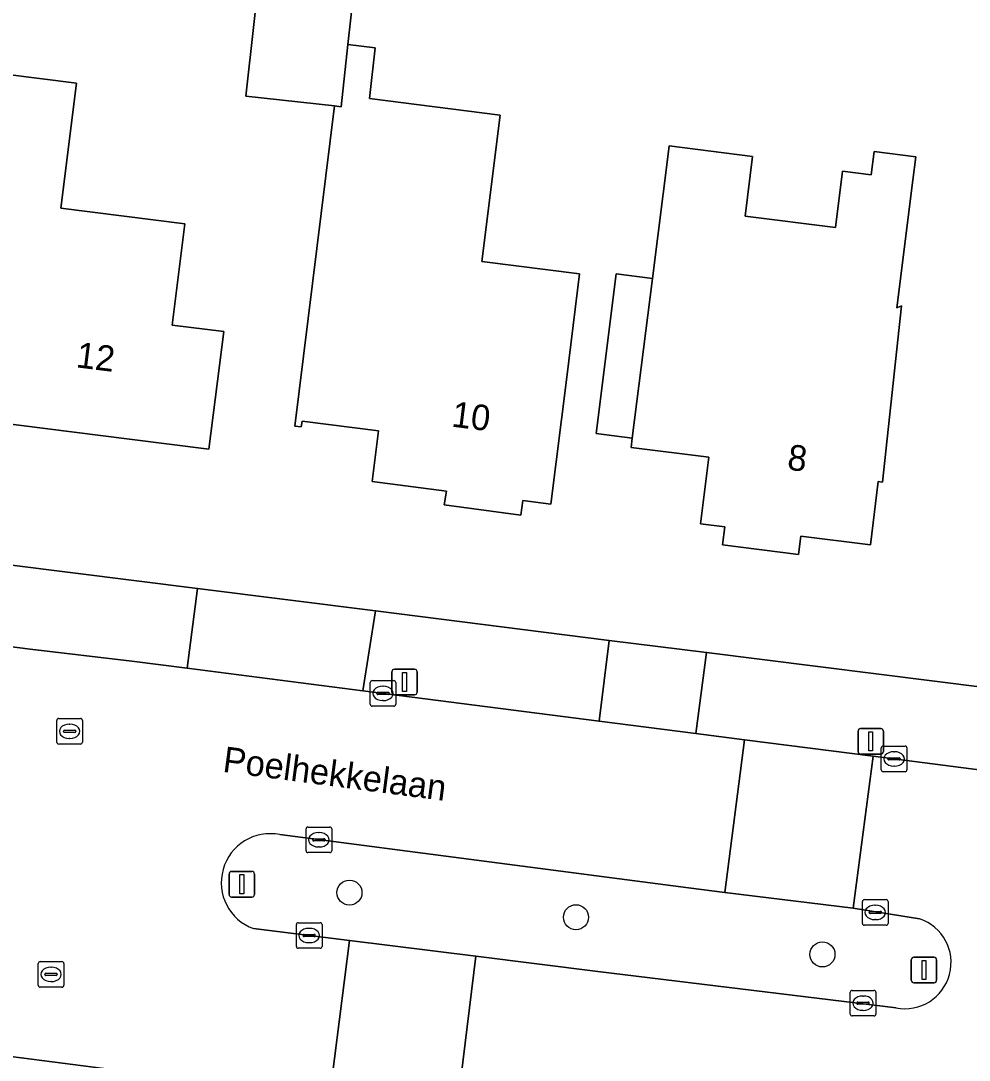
# Model space of a CAD drawing. Extents: x 161258 to 161838, y 380833 to 381727.
# Drawn here: x 161662.78 to 161699.84, y 381337.3 to 381377.89 of the extents above; entities that cross this region are included whole.
import ezdxf

# ---------------------------------------------------------------- set-up
doc = ezdxf.new("R2010")
doc.units = 0
for name, color, linetype in [('IMGEO_Berm_groen', 7, 'Continuous'), ('IMGEO_Boom', 7, 'Continuous'), ('IMGEO_Erf', 7, 'Continuous'), ('IMGEO_Kolk', 7, 'Continuous'), ('IMGEO_Lichtmast', 7, 'Continuous'), ('IMGEO_Openbare_ruimte_label', 7, 'Continuous'), ('IMGEO_Pand', 7, 'Continuous'), ('IMGEO_Pand_nummerreeks', 7, 'Continuous'), ('IMGEO_Rijbaan_lokaal_open', 7, 'Continuous'), ('IMGEO_Rioolput', 7, 'Continuous'), ('IMGEO_Verkeersbordpaal', 7, 'Continuous'), ('IMGEO_Voetpad_open', 7, 'Continuous')]:
    doc.layers.add(name, color=color, linetype=linetype)

msp = doc.modelspace()

# ---------------------------------------------------------------- linework, layer by layer
at = {"layer": 'IMGEO_Berm_groen'}
for points in [[(161695.307, 381343.233), (161690.292, 381343.852), (161688.874, 381344.034), (161672.903, 381346.109)], [(161697.905, 381342.825), (161695.307, 381343.233)], [(161671.878, 381342.439), (161675.625, 381341.974), (161680.569, 381341.362), (161685.333, 381340.771), (161696.981, 381339.343)]]:
    msp.add_lwpolyline(points, dxfattribs=at)
for centre, radius, start, end in [((161672.528, 381344.236), 1.911, 78.6811, 250.1097), ((161697.328, 381341.114), 1.805, 258.9062, 71.3703)]:
    msp.add_arc(centre, radius, start, end, dxfattribs=at)
at = {"layer": 'IMGEO_Boom'}
for centre in [(161675.627, 381343.846), (161684.477, 381342.885), (161694.108, 381341.432)]:
    msp.add_circle(centre, 0.489, dxfattribs=at)
at = {"layer": 'IMGEO_Erf'}
for points in [[(161649.876, 381358.212), (161669.686, 381355.721), (161676.646, 381354.846), (161685.778, 381353.698), (161689.572, 381353.221), (161700.55, 381351.841), (161703.323, 381376.439), (161703.682, 381379.623), (161710.363, 381438.89), (161702.199, 381460.88)], [(161675.92, 381380.099), (161675.568, 381376.965), (161676.626, 381376.832), (161676.405, 381374.855), (161681.514, 381374.212), (161680.793, 381368.487), (161684.619, 381368.006), (161684.113, 381363.979), (161683.489, 381359.018), (161682.396, 381359.155), (161682.32, 381358.586), (161679.33, 381358.984), (161679.421, 381359.53), (161676.507, 381359.896), (161676.757, 381361.886), (161673.774, 381362.255), (161673.745, 381362.031), (161673.486, 381362.065), (161675.044, 381374.567), (161671.58, 381374.956), (161672.207, 381380.555)]]:
    msp.add_lwpolyline(points, dxfattribs=at)
for points in [[(161664.964, 381375.453), (161664.351, 381370.574), (161669.196, 381369.965), (161668.698, 381366.006), (161670.713, 381365.753), (161670.136, 381361.169), (161667.027, 381361.559), (161660.531, 381362.376), (161660.47, 381361.885), (161655.947, 381362.454), (161656.003, 381362.9), (161652.899, 381363.29), (161653.522, 381368.251), (161654.621, 381377.046), (161658.181, 381376.613), (161657.832, 381373.841), (161661.873, 381373.334), (161662.175, 381375.804)], [(161696.014, 381371.878), (161696.128, 381372.789), (161697.755, 381372.585), (161697.64, 381371.674), (161697.012, 381366.68), (161697.195, 381366.757), (161696.455, 381359.88), (161696.29, 381359.901), (161695.978, 381357.422), (161693.256, 381357.764), (161693.166, 381357.052), (161690.204, 381357.425), (161690.293, 381358.129), (161689.341, 381358.249), (161689.668, 381360.851), (161686.632, 381361.234), (161686.678, 381361.597), (161685.265, 381361.775), (161686.049, 381368.013), (161687.462, 381367.833), (161688.086, 381372.794), (161688.113, 381373.009), (161691.379, 381372.599), (161691.085, 381370.267), (161694.615, 381369.824), (161694.891, 381372.019)]]:
    msp.add_lwpolyline(points, close=True, dxfattribs=at)
at = {"layer": 'IMGEO_Kolk'}
for p, q in [((161676.436, 381351.199), (161676.436, 381352.051)), ((161676.511, 381352.125), (161677.363, 381352.125)), ((161676.924, 381351.905), (161676.949, 381351.905)), ((161677.437, 381352.051), (161677.437, 381351.199)), ((161676.695, 381351.619), (161676.695, 381351.631)), ((161677.133, 381351.582), (161676.735, 381351.582)), ((161676.738, 381351.668), (161677.136, 381351.668)), ((161676.947, 381351.345), (161676.922, 381351.345)), ((161677.179, 381351.631), (161677.179, 381351.619)), ((161677.363, 381351.125), (161676.511, 381351.125)), ((161696.407, 381348.642), (161696.407, 381349.494)), ((161696.482, 381349.568), (161697.334, 381349.568)), ((161696.895, 381349.348), (161696.92, 381349.348)), ((161697.408, 381349.494), (161697.408, 381348.642)), ((161696.666, 381349.062), (161696.666, 381349.074)), ((161697.104, 381349.025), (161696.706, 381349.025)), ((161696.709, 381349.111), (161697.107, 381349.111)), ((161697.15, 381349.074), (161697.15, 381349.062)), ((161697.334, 381348.568), (161696.482, 381348.568)), ((161696.918, 381348.788), (161696.893, 381348.788)), ((161673.93, 381345.482), (161673.93, 381346.334)), ((161674.005, 381346.408), (161674.857, 381346.408)), ((161674.418, 381346.188), (161674.443, 381346.188)), ((161674.931, 381346.334), (161674.931, 381345.482)), ((161674.189, 381345.902), (161674.189, 381345.914)), ((161674.627, 381345.865), (161674.229, 381345.865)), ((161674.232, 381345.951), (161674.63, 381345.951)), ((161674.673, 381345.914), (161674.673, 381345.902)), ((161674.857, 381345.408), (161674.005, 381345.408)), ((161674.441, 381345.628), (161674.416, 381345.628)), ((161695.669, 381342.645), (161695.669, 381343.497)), ((161695.744, 381343.571), (161696.596, 381343.571)), ((161696.157, 381343.351), (161696.182, 381343.351)), ((161696.67, 381343.497), (161696.67, 381342.645)), ((161695.928, 381343.065), (161695.928, 381343.077)), ((161696.366, 381343.028), (161695.968, 381343.028)), ((161695.971, 381343.114), (161696.369, 381343.114)), ((161696.412, 381343.077), (161696.412, 381343.065)), ((161673.553, 381341.745), (161673.553, 381342.597)), ((161673.628, 381342.671), (161674.48, 381342.671)), ((161674.041, 381342.451), (161674.066, 381342.451)), ((161674.554, 381342.597), (161674.554, 381341.745)), ((161696.596, 381342.571), (161695.744, 381342.571)), ((161696.18, 381342.791), (161696.155, 381342.791)), ((161673.812, 381342.165), (161673.812, 381342.177)), ((161674.25, 381342.128), (161673.852, 381342.128)), ((161673.855, 381342.214), (161674.253, 381342.214)), ((161674.296, 381342.177), (161674.296, 381342.165)), ((161674.48, 381341.671), (161673.628, 381341.671)), ((161674.064, 381341.891), (161674.039, 381341.891)), ((161695.267, 381340.028), (161696.119, 381340.028)), ((161695.192, 381339.102), (161695.192, 381339.954)), ((161695.68, 381339.808), (161695.705, 381339.808)), ((161696.193, 381339.954), (161696.193, 381339.102)), ((161695.451, 381339.522), (161695.451, 381339.534)), ((161695.889, 381339.485), (161695.491, 381339.485)), ((161695.494, 381339.571), (161695.892, 381339.571)), ((161695.703, 381339.248), (161695.678, 381339.248)), ((161695.935, 381339.534), (161695.935, 381339.522)), ((161696.119, 381339.028), (161695.267, 381339.028))]:
    msp.add_line(p, q, dxfattribs=at)
for points in [[(161676.436, 381351.199), (161676.436, 381352.051)], [(161676.511, 381352.125), (161677.363, 381352.125)], [(161677.437, 381352.051), (161677.437, 381351.199)], [(161677.363, 381351.125), (161676.511, 381351.125)], [(161696.407, 381348.642), (161696.407, 381349.494)], [(161696.482, 381349.568), (161697.334, 381349.568)], [(161697.408, 381349.494), (161697.408, 381348.642)], [(161697.334, 381348.568), (161696.482, 381348.568)], [(161673.93, 381345.482), (161673.93, 381346.334)], [(161674.005, 381346.408), (161674.857, 381346.408)], [(161674.931, 381346.334), (161674.931, 381345.482)], [(161674.857, 381345.408), (161674.005, 381345.408)], [(161695.669, 381342.645), (161695.669, 381343.497)], [(161695.744, 381343.571), (161696.596, 381343.571)], [(161696.67, 381343.497), (161696.67, 381342.645)], [(161673.553, 381341.745), (161673.553, 381342.597)], [(161673.628, 381342.671), (161674.48, 381342.671)], [(161674.554, 381342.597), (161674.554, 381341.745)], [(161696.596, 381342.571), (161695.744, 381342.571)], [(161674.48, 381341.671), (161673.628, 381341.671)], [(161695.267, 381340.028), (161696.119, 381340.028)], [(161695.192, 381339.102), (161695.192, 381339.954)], [(161696.193, 381339.954), (161696.193, 381339.102)], [(161696.119, 381339.028), (161695.267, 381339.028)]]:
    msp.add_lwpolyline(points, dxfattribs=at)
for centre, radius, start, end in [((161676.513, 381352.049), 0.0765, 91.552, 178.448), ((161676.513, 381352.049), 0.0765, 91.552, 178.448), ((161677.361, 381352.049), 0.0765, 1.552, 88.448), ((161677.361, 381352.049), 0.0765, 1.552, 88.448), ((161676.735, 381351.628), 0.0403, 85.8775, 175.7526), ((161676.732, 381351.618), 0.0366, 178.938, 274.7102), ((161677.136, 381351.625), 0.043, 264.8664, 352.4533), ((161677.14, 381351.63), 0.0386, 1.7309, 96.639), ((161676.513, 381351.201), 0.0765, 181.552, 268.448), ((161676.513, 381351.201), 0.0765, 181.552, 268.448), ((161677.361, 381351.201), 0.0765, 271.552, 358.448), ((161677.361, 381351.201), 0.0765, 271.552, 358.448), ((161696.484, 381349.492), 0.0765, 91.552, 178.448), ((161696.484, 381349.492), 0.0765, 91.552, 178.448), ((161697.332, 381349.492), 0.0765, 1.552, 88.448), ((161697.332, 381349.492), 0.0765, 1.552, 88.448), ((161696.706, 381349.071), 0.0403, 85.8775, 175.7526), ((161696.703, 381349.061), 0.0366, 178.938, 274.7102), ((161697.107, 381349.068), 0.043, 264.8664, 352.4533), ((161697.111, 381349.073), 0.0386, 1.7309, 96.639), ((161696.484, 381348.644), 0.0765, 181.552, 268.448), ((161696.484, 381348.644), 0.0765, 181.552, 268.448), ((161697.332, 381348.644), 0.0765, 271.552, 358.448), ((161697.332, 381348.644), 0.0765, 271.552, 358.448), ((161674.007, 381346.332), 0.0765, 91.552, 178.448), ((161674.007, 381346.332), 0.0765, 91.552, 178.448), ((161674.855, 381346.332), 0.0765, 1.552, 88.448), ((161674.855, 381346.332), 0.0765, 1.552, 88.448), ((161674.229, 381345.911), 0.0403, 85.8775, 175.7526), ((161674.226, 381345.901), 0.0366, 178.938, 274.7102), ((161674.63, 381345.908), 0.043, 264.8664, 352.4533), ((161674.634, 381345.913), 0.0386, 1.7309, 96.639), ((161674.007, 381345.484), 0.0765, 181.552, 268.448), ((161674.007, 381345.484), 0.0765, 181.552, 268.448), ((161674.855, 381345.484), 0.0765, 271.552, 358.448), ((161674.855, 381345.484), 0.0765, 271.552, 358.448), ((161695.746, 381343.495), 0.0765, 91.552, 178.448), ((161695.746, 381343.495), 0.0765, 91.552, 178.448), ((161696.594, 381343.495), 0.0765, 1.552, 88.448), ((161696.594, 381343.495), 0.0765, 1.552, 88.448), ((161695.968, 381343.074), 0.0403, 85.8775, 175.7526), ((161695.965, 381343.064), 0.0366, 178.938, 274.7102), ((161696.369, 381343.071), 0.043, 264.8664, 352.4533), ((161696.373, 381343.076), 0.0386, 1.7309, 96.639), ((161673.63, 381342.595), 0.0765, 91.552, 178.448), ((161673.63, 381342.595), 0.0765, 91.552, 178.448), ((161674.478, 381342.595), 0.0765, 1.552, 88.448), ((161674.478, 381342.595), 0.0765, 1.552, 88.448), ((161695.746, 381342.647), 0.0765, 181.552, 268.448), ((161695.746, 381342.647), 0.0765, 181.552, 268.448), ((161696.594, 381342.647), 0.0765, 271.552, 358.448), ((161696.594, 381342.647), 0.0765, 271.552, 358.448), ((161673.852, 381342.174), 0.0403, 85.8775, 175.7526), ((161673.849, 381342.164), 0.0366, 178.938, 274.7102), ((161674.253, 381342.171), 0.043, 264.8664, 352.4533), ((161674.257, 381342.176), 0.0386, 1.7309, 96.639), ((161673.63, 381341.747), 0.0765, 181.552, 268.448), ((161673.63, 381341.747), 0.0765, 181.552, 268.448), ((161674.478, 381341.747), 0.0765, 271.552, 358.448), ((161674.478, 381341.747), 0.0765, 271.552, 358.448), ((161695.269, 381339.952), 0.0765, 91.552, 178.448), ((161695.269, 381339.952), 0.0765, 91.552, 178.448), ((161696.117, 381339.952), 0.0765, 1.552, 88.448), ((161696.117, 381339.952), 0.0765, 1.552, 88.448), ((161695.491, 381339.531), 0.0403, 85.8775, 175.7526), ((161695.488, 381339.521), 0.0366, 178.938, 274.7102), ((161695.892, 381339.528), 0.043, 264.8664, 352.4533), ((161695.896, 381339.533), 0.0386, 1.7309, 96.639), ((161695.269, 381339.104), 0.0765, 181.552, 268.448), ((161695.269, 381339.104), 0.0765, 181.552, 268.448), ((161696.117, 381339.104), 0.0765, 271.552, 358.448), ((161696.117, 381339.104), 0.0765, 271.552, 358.448)]:
    msp.add_arc(centre, radius, start, end, dxfattribs=at)
for centre, major_axis, ratio, start_param, end_param in [((161676.923, 381351.625), (-0.387, 0.002), 0.722429, 4.712389, 7.853982), ((161676.948, 381351.625), (-0.39, 0.002), 0.717154, 1.570796, 4.712389), ((161696.894, 381349.068), (-0.387, 0.002), 0.722429, 4.712389, 7.853982), ((161696.919, 381349.068), (-0.39, 0.002), 0.717154, 1.570796, 4.712389), ((161674.417, 381345.908), (-0.387, 0.002), 0.722429, 4.712389, 7.853982), ((161674.442, 381345.908), (-0.39, 0.002), 0.717154, 1.570796, 4.712389), ((161696.156, 381343.071), (-0.387, 0.002), 0.722429, 4.712389, 7.853982), ((161696.181, 381343.071), (-0.39, 0.002), 0.717154, 1.570796, 4.712389), ((161674.04, 381342.171), (-0.387, 0.002), 0.722429, 4.712389, 7.853982), ((161674.065, 381342.171), (-0.39, 0.002), 0.717154, 1.570796, 4.712389), ((161695.679, 381339.528), (-0.387, 0.002), 0.722429, 4.712389, 7.853982), ((161695.704, 381339.528), (-0.39, 0.002), 0.717154, 1.570796, 4.712389)]:
    msp.add_ellipse(centre, major_axis=major_axis, ratio=ratio, start_param=start_param, end_param=end_param, dxfattribs=at)
at = {"layer": 'IMGEO_Lichtmast'}
for p, q in [((161677.381, 381352.573), (161678.171, 381352.573)), ((161678.171, 381352.573), (161677.381, 381352.573)), ((161677.281, 381351.673), (161677.281, 381352.473)), ((161677.281, 381352.473), (161677.281, 381351.673)), ((161678.271, 381352.473), (161678.271, 381351.673)), ((161678.271, 381351.673), (161678.271, 381352.473)), ((161678.171, 381351.573), (161677.381, 381351.573)), ((161677.381, 381351.573), (161678.171, 381351.573)), ((161695.498, 381349.352), (161695.498, 381350.152)), ((161695.498, 381350.152), (161695.498, 381349.352)), ((161695.598, 381350.252), (161696.388, 381350.252)), ((161696.388, 381350.252), (161695.598, 381350.252)), ((161696.488, 381350.152), (161696.488, 381349.352)), ((161696.488, 381349.352), (161696.488, 381350.152)), ((161696.388, 381349.252), (161695.598, 381349.252)), ((161695.598, 381349.252), (161696.388, 381349.252))]:
    msp.add_line(p, q, dxfattribs=at)
for points in [[(161677.701, 381352.448), (161677.851, 381352.448), (161677.851, 381351.698), (161677.701, 381351.698), (161677.701, 381352.448)], [(161695.918, 381350.127), (161696.068, 381350.127), (161696.068, 381349.377), (161695.918, 381349.377), (161695.918, 381350.127)]]:
    msp.add_lwpolyline(points, dxfattribs=at)
for centre, start, end in [((161677.381, 381352.473), 90, 180), ((161677.381, 381352.473), 90, 180), ((161678.171, 381352.473), 0, 90), ((161678.171, 381352.473), 360, 90), ((161677.381, 381351.673), 180, 270), ((161677.381, 381351.673), 180, 270), ((161678.171, 381351.673), 270, 0), ((161678.171, 381351.673), 270, 0), ((161695.598, 381350.152), 90, 180), ((161695.598, 381350.152), 90, 180), ((161696.388, 381350.152), 0, 90), ((161696.388, 381350.152), 360, 90), ((161695.598, 381349.352), 180, 270), ((161695.598, 381349.352), 180, 270), ((161696.388, 381349.352), 270, 0), ((161696.388, 381349.352), 270, 0)]:
    msp.add_arc(centre, 0.1, start, end, dxfattribs=at)
at = {"layer": 'IMGEO_Pand'}
for points in [[(161675.92, 381380.099), (161675.099, 381380.191), (161672.207, 381380.555), (161671.58, 381374.956), (161675.044, 381374.567), (161675.297, 381374.539), (161675.568, 381376.965)], [(161684.619, 381368.006), (161680.793, 381368.487), (161681.514, 381374.212), (161676.405, 381374.855), (161676.626, 381376.832), (161675.568, 381376.965), (161675.297, 381374.539), (161675.044, 381374.567), (161673.486, 381362.065), (161673.745, 381362.031), (161673.774, 381362.255), (161676.757, 381361.886), (161676.507, 381359.896), (161679.421, 381359.53), (161679.33, 381358.984), (161682.32, 381358.586), (161682.396, 381359.155), (161683.489, 381359.018), (161684.113, 381363.979)], [(161669.196, 381369.965), (161664.351, 381370.574), (161664.964, 381375.453), (161662.175, 381375.804), (161661.873, 381373.334), (161660.531, 381362.376), (161667.027, 381361.559), (161670.136, 381361.169), (161670.713, 381365.753), (161668.698, 381366.006)], [(161697.195, 381366.757), (161697.012, 381366.68), (161697.64, 381371.674), (161697.755, 381372.585), (161696.128, 381372.789), (161696.014, 381371.878), (161694.891, 381372.019), (161694.615, 381369.824), (161691.085, 381370.267), (161691.379, 381372.599), (161688.113, 381373.009), (161688.086, 381372.794), (161687.462, 381367.833), (161686.678, 381361.597), (161686.632, 381361.234), (161689.668, 381360.851), (161689.341, 381358.249), (161690.293, 381358.129), (161690.204, 381357.425), (161693.166, 381357.052), (161693.256, 381357.764), (161695.978, 381357.422), (161696.29, 381359.901), (161696.455, 381359.88)], [(161687.462, 381367.833), (161686.049, 381368.013), (161685.265, 381361.775), (161686.678, 381361.597)]]:
    msp.add_lwpolyline(points, close=True, dxfattribs=at)
at = {"layer": 'IMGEO_Rijbaan_lokaal_open'}
for points in [[(161672.903, 381346.109), (161688.874, 381344.034), (161690.292, 381343.852), (161691.062, 381349.816), (161689.165, 381350.059), (161685.382, 381350.543), (161676.146, 381351.726), (161669.284, 381352.605), (161667.128, 381352.881), (161663.154, 381353.357), (161649.504, 381355.102), (161646.108, 381355.537), (161640.396, 381356.267), (161639.527, 381350.255), (161646.91, 381349.34), (161656.896, 381348.015)], [(161615.494, 381349.658), (161611.074, 381350.179), (161610.322, 381344.022), (161617.366, 381343.162), (161619.037, 381342.946), (161619.159, 381342.93), (161622.743, 381342.5), (161629.126, 381341.734), (161631.389, 381341.442), (161638.808, 381340.484), (161640.8, 381340.227), (161650.536, 381338.943), (161657.935, 381338.014), (161669.261, 381336.557), (161669.258, 381336.54), (161674.844, 381335.829), (161675.625, 381341.974), (161671.878, 381342.439)], [(161708.88, 381346.759), (161708.995, 381347.495), (161708.497, 381347.56), (161701.97, 381348.417), (161701.538, 381348.474), (161696.089, 381349.172), (161695.307, 381343.233), (161697.905, 381342.825)], [(161696.981, 381339.343), (161685.333, 381340.771), (161680.569, 381341.362), (161679.804, 381335.202), (161687.626, 381334.23), (161690.979, 381333.814), (161700.036, 381332.619), (161701.883, 381332.375)], [(161669.258, 381336.54), (161669.261, 381336.557), (161657.935, 381338.014)]]:
    msp.add_lwpolyline(points, dxfattribs=at)
for points in [[(161696.089, 381349.172), (161691.062, 381349.816), (161690.292, 381343.852), (161695.307, 381343.233)], [(161674.844, 381335.829), (161678.715, 381335.337), (161679.804, 381335.202), (161680.569, 381341.362), (161675.625, 381341.974)]]:
    msp.add_lwpolyline(points, close=True, dxfattribs=at)
for centre, radius, start, end in [((161672.528, 381344.236), 1.911, 78.6811, 250.1097), ((161697.328, 381341.114), 1.805, 258.9062, 71.3703)]:
    msp.add_arc(centre, radius, start, end, dxfattribs=at)
at = {"layer": 'IMGEO_Rioolput'}
for p, q in [((161664.191, 381349.721), (161664.191, 381350.573)), ((161664.266, 381350.647), (161665.118, 381350.647)), ((161665.192, 381350.573), (161665.192, 381349.721)), ((161664.45, 381350.141), (161664.45, 381350.153)), ((161664.493, 381350.19), (161664.891, 381350.19)), ((161664.679, 381350.427), (161664.704, 381350.427)), ((161664.934, 381350.153), (161664.934, 381350.141)), ((161664.888, 381350.104), (161664.49, 381350.104)), ((161664.702, 381349.867), (161664.677, 381349.867)), ((161665.118, 381349.647), (161664.266, 381349.647)), ((161663.466, 381340.225), (161663.466, 381341.077)), ((161663.541, 381341.151), (161664.393, 381341.151)), ((161663.954, 381340.931), (161663.979, 381340.931)), ((161664.467, 381341.077), (161664.467, 381340.225)), ((161663.725, 381340.645), (161663.725, 381340.657)), ((161664.163, 381340.608), (161663.765, 381340.608)), ((161663.768, 381340.694), (161664.166, 381340.694)), ((161664.209, 381340.657), (161664.209, 381340.645)), ((161664.393, 381340.151), (161663.541, 381340.151)), ((161663.977, 381340.371), (161663.952, 381340.371))]:
    msp.add_line(p, q, dxfattribs=at)
for points in [[(161664.191, 381349.721), (161664.191, 381350.573)], [(161664.266, 381350.647), (161665.118, 381350.647)], [(161665.192, 381350.573), (161665.192, 381349.721)], [(161665.118, 381349.647), (161664.266, 381349.647)], [(161663.466, 381340.225), (161663.466, 381341.077)], [(161663.541, 381341.151), (161664.393, 381341.151)], [(161664.467, 381341.077), (161664.467, 381340.225)], [(161664.393, 381340.151), (161663.541, 381340.151)]]:
    msp.add_lwpolyline(points, dxfattribs=at)
for centre, radius, start, end in [((161664.268, 381350.571), 0.0765, 91.552, 178.448), ((161664.268, 381350.571), 0.0765, 91.552, 178.448), ((161665.116, 381350.571), 0.0765, 1.552, 88.448), ((161665.116, 381350.571), 0.0765, 1.552, 88.448), ((161664.49, 381350.15), 0.0403, 85.8775, 175.7526), ((161664.487, 381350.14), 0.0366, 178.938, 274.7102), ((161664.891, 381350.147), 0.043, 264.8664, 352.4533), ((161664.895, 381350.152), 0.0386, 1.7309, 96.639), ((161664.268, 381349.723), 0.0765, 181.552, 268.448), ((161664.268, 381349.723), 0.0765, 181.552, 268.448), ((161665.116, 381349.723), 0.0765, 271.552, 358.448), ((161665.116, 381349.723), 0.0765, 271.552, 358.448), ((161663.543, 381341.075), 0.0765, 91.552, 178.448), ((161663.543, 381341.075), 0.0765, 91.552, 178.448), ((161664.391, 381341.075), 0.0765, 1.552, 88.448), ((161664.391, 381341.075), 0.0765, 1.552, 88.448), ((161663.765, 381340.654), 0.0403, 85.8775, 175.7526), ((161663.762, 381340.644), 0.0366, 178.938, 274.7102), ((161664.166, 381340.651), 0.043, 264.8664, 352.4533), ((161664.17, 381340.656), 0.0386, 1.7309, 96.639), ((161663.543, 381340.227), 0.0765, 181.552, 268.448), ((161663.543, 381340.227), 0.0765, 181.552, 268.448), ((161664.391, 381340.227), 0.0765, 271.552, 358.448), ((161664.391, 381340.227), 0.0765, 271.552, 358.448)]:
    msp.add_arc(centre, radius, start, end, dxfattribs=at)
for centre, major_axis, ratio, start_param, end_param in [((161664.678, 381350.147), (-0.387, 0.002), 0.722429, 4.712389, 7.853982), ((161664.703, 381350.147), (-0.39, 0.002), 0.717154, 1.570796, 4.712389), ((161663.953, 381340.651), (-0.387, 0.002), 0.722429, 4.712389, 7.853982), ((161663.978, 381340.651), (-0.39, 0.002), 0.717154, 1.570796, 4.712389)]:
    msp.add_ellipse(centre, major_axis=major_axis, ratio=ratio, start_param=start_param, end_param=end_param, dxfattribs=at)
at = {"layer": 'IMGEO_Verkeersbordpaal'}
for p, q in [((161670.923, 381343.772), (161670.923, 381344.572)), ((161670.923, 381344.572), (161670.923, 381343.772)), ((161671.023, 381344.672), (161671.813, 381344.672)), ((161671.813, 381344.672), (161671.023, 381344.672)), ((161671.913, 381344.572), (161671.913, 381343.772)), ((161671.913, 381343.772), (161671.913, 381344.572)), ((161671.813, 381343.672), (161671.023, 381343.672)), ((161671.023, 381343.672), (161671.813, 381343.672)), ((161697.577, 381340.423), (161697.577, 381341.223)), ((161697.577, 381341.223), (161697.577, 381340.423)), ((161697.677, 381341.323), (161698.467, 381341.323)), ((161698.467, 381341.323), (161697.677, 381341.323)), ((161698.567, 381341.223), (161698.567, 381340.423)), ((161698.567, 381340.423), (161698.567, 381341.223)), ((161698.467, 381340.323), (161697.677, 381340.323)), ((161697.677, 381340.323), (161698.467, 381340.323))]:
    msp.add_line(p, q, dxfattribs=at)
for points in [[(161671.343, 381344.547), (161671.493, 381344.547), (161671.493, 381343.797), (161671.343, 381343.797), (161671.343, 381344.547)], [(161697.997, 381341.198), (161698.147, 381341.198), (161698.147, 381340.448), (161697.997, 381340.448), (161697.997, 381341.198)]]:
    msp.add_lwpolyline(points, dxfattribs=at)
for centre, start, end in [((161671.023, 381344.572), 90, 180), ((161671.023, 381344.572), 90, 180), ((161671.813, 381344.572), 0, 90), ((161671.813, 381344.572), 360, 90), ((161671.023, 381343.772), 180, 270), ((161671.023, 381343.772), 180, 270), ((161671.813, 381343.772), 270, 0), ((161671.813, 381343.772), 270, 0), ((161697.677, 381341.223), 90, 180), ((161697.677, 381341.223), 90, 180), ((161698.467, 381341.223), 0, 90), ((161698.467, 381341.223), 360, 90), ((161697.677, 381340.423), 180, 270), ((161697.677, 381340.423), 180, 270), ((161698.467, 381340.423), 270, 0), ((161698.467, 381340.423), 270, 0)]:
    msp.add_arc(centre, 0.1, start, end, dxfattribs=at)
at = {"layer": 'IMGEO_Voetpad_open'}
for points in [[(161669.686, 381355.721), (161649.876, 381358.212), (161649.504, 381355.102), (161663.154, 381353.357), (161667.128, 381352.881), (161669.284, 381352.605)], [(161676.646, 381354.846), (161669.686, 381355.721), (161669.284, 381352.605), (161676.146, 381351.726)], [(161685.778, 381353.698), (161676.646, 381354.846), (161676.146, 381351.726), (161685.382, 381350.543)], [(161689.572, 381353.221), (161685.778, 381353.698), (161685.382, 381350.543), (161689.165, 381350.059)]]:
    msp.add_lwpolyline(points, close=True, dxfattribs=at)
msp.add_lwpolyline([(161704.663, 381351.215), (161700.57, 381351.838), (161700.55, 381351.841), (161689.572, 381353.221), (161689.165, 381350.059), (161691.062, 381349.816), (161696.089, 381349.172), (161701.538, 381348.474), (161701.97, 381348.417), (161708.497, 381347.56), (161708.995, 381347.495), (161708.88, 381346.759)], dxfattribs=at)

# ---------------------------------------------------------------- texts
at = {"layer": 'IMGEO_Openbare_ruimte_label'}
msp.add_text('Poelhekkelaan', height=1, rotation=352.534, dxfattribs=at).set_placement((161670.643, 381348.567))
at = {"layer": 'IMGEO_Pand_nummerreeks'}
for s, rotation, p in [('12', 352.838, (161664.915, 381364.365)), ('10', 352.8323, (161679.586, 381362.048)), ('8', 352.8953, (161692.701, 381360.37))]:
    msp.add_text(s, height=1, rotation=rotation, dxfattribs=at).set_placement(p)

doc.saveas('drawing.dxf')
